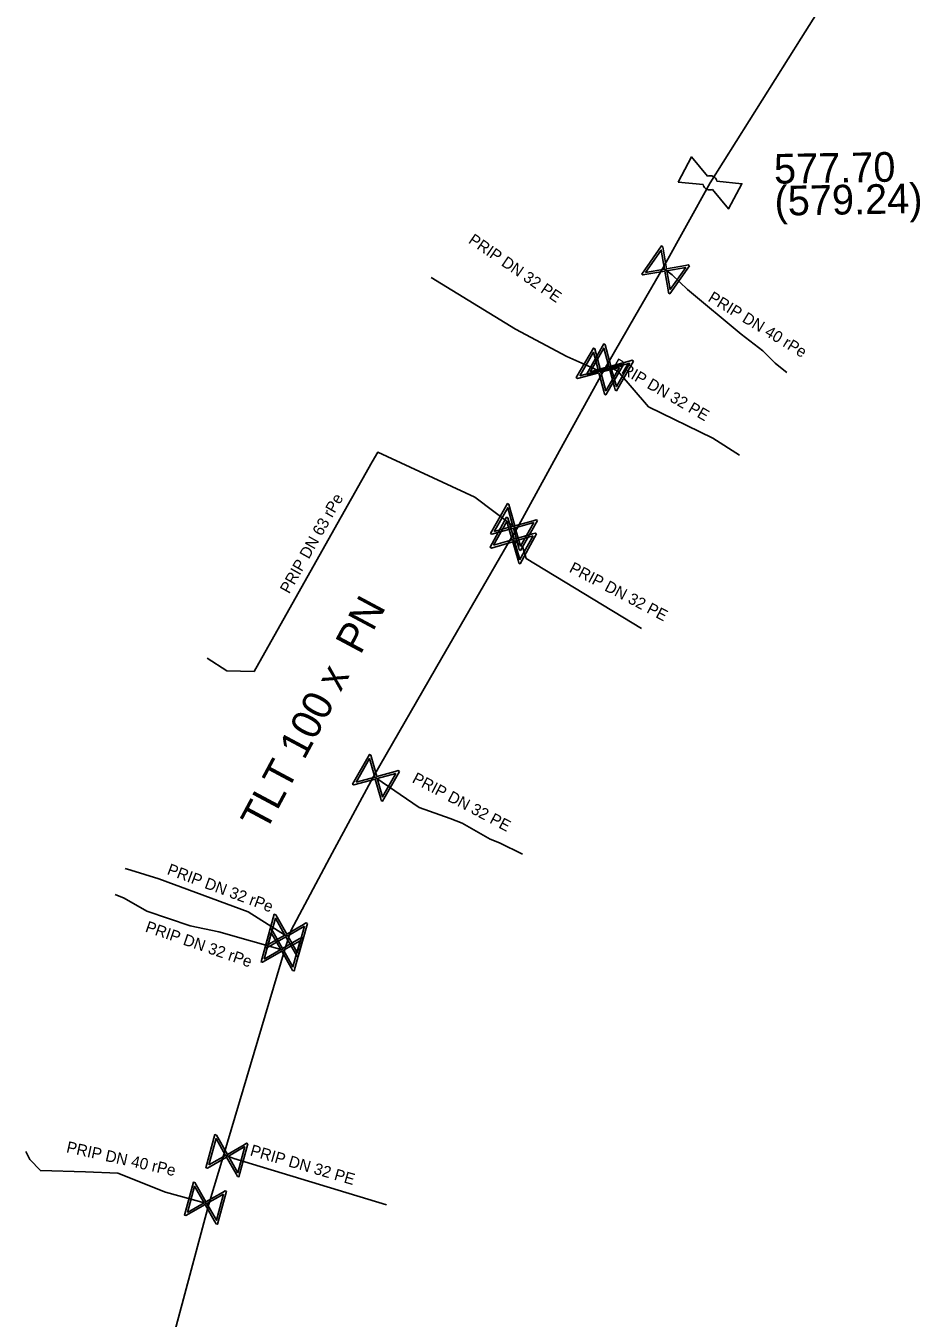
# Model space of a CAD drawing. Extents: x -643544 to -637295, y -1119190 to -1111715.
# Drawn here: x -641860.3 to -641821.1, y -1114876.1 to -1114819.6 of the extents above; entities that cross this region are included whole.
import ezdxf

# ---------------------------------------------------------------- set-up
doc = ezdxf.new("R2010")
doc.units = 0
for name, color, linetype in [('Default', 7, 'Continuous'), ('VP Lomový bod', 7, 'Continuous'), ('VP Lomový bod - popis', 7, 'Continuous'), ('VP Popis přípojky', 7, 'Continuous'), ('VP Přípojka', 7, 'Continuous'), ('VP Řad', 7, 'Continuous'), ('VP Řad - popis', 7, 'Continuous'), ('VP Šoupě', 7, 'Continuous')]:
    doc.layers.add(name, color=color, linetype=linetype)

msp = doc.modelspace()

# ---------------------------------------------------------------- linework, layer by layer
at = {"layer": 'Default'}
for points in [[(-641830.444, -1114826.137), (-641830.395, -1114826.119), (-641830.342, -1114826.117), (-641830.255, -1114826.116), (-641830.183, -1114826.154), (-641830.111, -1114826.193), (-641830.066, -1114826.264), (-641830.036, -1114826.31), (-641830.025, -1114826.361)], [(-641830.217, -1114826.721), (-641830.266, -1114826.741), (-641830.321, -1114826.742), (-641830.405, -1114826.744), (-641830.477, -1114826.706), (-641830.549, -1114826.667), (-641830.596, -1114826.594), (-641830.625, -1114826.55), (-641830.636, -1114826.498)]]:
    msp.add_open_spline(points, degree=3, dxfattribs=at)
at = {"layer": 'VP Lomový bod'}
for points in [[(-641831.727, -1114826.394), (-641831.139, -1114825.291), (-641830.444, -1114826.137)], [(-641830.636, -1114826.498), (-641831.727, -1114826.394)], [(-641830.025, -1114826.361), (-641828.933, -1114826.466), (-641829.521, -1114827.569), (-641830.217, -1114826.721)]]:
    msp.add_lwpolyline(points, dxfattribs=at)
at = {"layer": 'VP Přípojka'}
for points in [[(-641832.39, -1114830.16), (-641832.273, -1114830.238), (-641831.98, -1114830.45), (-641831.32, -1114831.1), (-641828.97, -1114833.05), (-641828.02, -1114833.78), (-641827.48, -1114834.32), (-641827.1, -1114834.63), (-641826.972, -1114834.735)], [(-641835.04, -1114834.75), (-641835.151, -1114834.676), (-641836.59, -1114834.03), (-641838.85, -1114832.84), (-641842.534, -1114830.571)], [(-641829.046, -1114838.345), (-641830.21, -1114837.6), (-641833.02, -1114836.23), (-641834.37, -1114834.67), (-641834.722, -1114834.486), (-641834.84, -1114834.41)], [(-641838.79, -1114841.57), (-641838.907, -1114841.492), (-641840.62, -1114840.19), (-641844.87, -1114838.22), (-641845.11, -1114838.64), (-641846.92, -1114841.85), (-641850.28, -1114847.81), (-641851.47, -1114847.79), (-641852.331, -1114847.228)], [(-641839.06, -1114842.02), (-641838.936, -1114842.085), (-641838.85, -1114842.13), (-641838.75, -1114842.21), (-641838.54, -1114842.35), (-641838.37, -1114842.87), (-641833.334, -1114845.941)], [(-641845.06, -1114852.41), (-641844.955, -1114852.478), (-641843.06, -1114853.77), (-641841.7, -1114854.25), (-641841.18, -1114854.45), (-641839.95, -1114855.15), (-641839.55, -1114855.31), (-641838.54, -1114855.81)], [(-641855.927, -1114856.434), (-641855.68, -1114856.51), (-641854.45, -1114856.89), (-641850.54, -1114858.34), (-641848.95, -1114859.35), (-641848.872, -1114859.366), (-641848.75, -1114859.39)], [(-641856.368, -1114857.574), (-641855.97, -1114857.74), (-641854.97, -1114858.3), (-641853.08, -1114858.95), (-641851.82, -1114859.21), (-641849.057, -1114860), (-641848.95, -1114860.03)], [(-641860.27, -1114868.82), (-641860.1, -1114869.17), (-641859.63, -1114869.66), (-641857.66, -1114869.72), (-641856.25, -1114869.77), (-641854.16, -1114870.61), (-641852.41, -1114871.09), (-641852.26, -1114871.13)], [(-641851.6, -1114868.96), (-641851.165, -1114869.129), (-641844.492, -1114871.16)]]:
    msp.add_lwpolyline(points, dxfattribs=at)
at = {"layer": 'VP Řad'}
msp.add_lwpolyline([(-641854.93, -1114881.05), (-641853.595, -1114876.09), (-641852.26, -1114871.13), (-641851.6, -1114868.96), (-641850.275, -1114864.495), (-641848.95, -1114860.03), (-641848.75, -1114859.39), (-641848.66, -1114859.14), (-641846.86, -1114855.775), (-641845.06, -1114852.41), (-641842.06, -1114847.215), (-641839.06, -1114842.02), (-641838.79, -1114841.57), (-641836.915, -1114838.16), (-641835.04, -1114834.75), (-641834.84, -1114834.41), (-641833.615, -1114832.285), (-641832.39, -1114830.16), (-641830.33, -1114826.43), (-641826.335, -1114820.09), (-641822.34, -1114813.75)], dxfattribs=at)
at = {"layer": 'VP Šoupě'}
for points in [[(-641831.228, -1114830.056), (-641832.091, -1114831.283), (-641832.145, -1114831.245), (-641832.163, -1114831.118), (-641832.308, -1114830.29), (-641833.264, -1114830.458), (-641833.318, -1114830.42), (-641832.455, -1114829.193), (-641832.401, -1114829.231), (-641832.236, -1114830.189), (-641831.409, -1114830.043), (-641831.282, -1114830.018), (-641831.228, -1114830.056)], [(-641833.154, -1114830.349), (-641832.323, -1114830.204), (-641832.468, -1114829.375), (-641833.154, -1114830.349)], [(-641831.395, -1114830.131), (-641832.221, -1114830.275), (-641832.077, -1114831.1), (-641831.395, -1114830.131)], [(-641833.68, -1114834.229), (-641834.428, -1114835.529), (-641834.485, -1114835.496), (-641834.514, -1114835.371), (-641834.734, -1114834.56), (-641835.671, -1114834.814), (-641835.728, -1114834.782), (-641834.981, -1114833.481), (-641834.924, -1114833.514), (-641834.672, -1114834.452), (-641833.862, -1114834.232), (-641833.737, -1114834.196), (-641833.68, -1114834.229)], [(-641834.133, -1114834.416), (-641834.89, -1114835.711), (-641834.947, -1114835.678), (-641834.976, -1114835.553), (-641835.19, -1114834.74), (-641836.128, -1114834.987), (-641836.185, -1114834.954), (-641835.428, -1114833.659), (-641835.371, -1114833.692), (-641835.127, -1114834.633), (-641834.314, -1114834.419), (-641834.19, -1114834.383), (-641834.133, -1114834.416)], [(-641836.027, -1114834.87), (-641835.212, -1114834.655), (-641835.426, -1114833.842), (-641836.027, -1114834.87)], [(-641835.571, -1114834.696), (-641834.757, -1114834.475), (-641834.978, -1114833.664), (-641835.571, -1114834.696)], [(-641834.293, -1114834.505), (-641835.104, -1114834.718), (-641834.891, -1114835.527), (-641834.293, -1114834.505)], [(-641833.84, -1114834.318), (-641834.649, -1114834.537), (-641834.43, -1114835.345), (-641833.84, -1114834.318)], [(-641837.884, -1114841.212), (-641838.627, -1114842.515), (-641838.685, -1114842.482), (-641838.715, -1114842.357), (-641838.937, -1114841.547), (-641839.873, -1114841.804), (-641839.93, -1114841.772), (-641839.187, -1114840.469), (-641839.129, -1114840.502), (-641838.875, -1114841.439), (-641838.065, -1114841.217), (-641837.941, -1114841.18), (-641837.884, -1114841.212)], [(-641839.773, -1114841.686), (-641838.96, -1114841.463), (-641839.183, -1114840.651), (-641839.773, -1114841.686)], [(-641837.917, -1114841.79), (-641838.641, -1114843.104), (-641838.698, -1114843.072), (-641838.73, -1114842.947), (-641838.965, -1114842.141), (-641839.897, -1114842.412), (-641839.955, -1114842.38), (-641839.231, -1114841.066), (-641839.174, -1114841.098), (-641838.905, -1114842.032), (-641838.099, -1114841.797), (-641837.975, -1114841.758), (-641837.917, -1114841.79)], [(-641839.799, -1114842.292), (-641838.99, -1114842.056), (-641839.225, -1114841.249), (-641839.799, -1114842.292)], [(-641838.043, -1114841.303), (-641838.852, -1114841.524), (-641838.63, -1114842.331), (-641838.043, -1114841.303)], [(-641838.075, -1114841.882), (-641838.881, -1114842.116), (-641838.646, -1114842.92), (-641838.075, -1114841.882)], [(-641843.926, -1114852.188), (-641844.666, -1114853.493), (-641844.724, -1114853.46), (-641844.754, -1114853.335), (-641844.978, -1114852.526), (-641845.914, -1114852.785), (-641845.971, -1114852.752), (-641845.231, -1114851.448), (-641845.173, -1114851.48), (-641844.917, -1114852.417), (-641844.107, -1114852.193), (-641843.983, -1114852.155), (-641843.926, -1114852.188)], [(-641845.814, -1114852.666), (-641845.002, -1114852.441), (-641845.226, -1114851.63), (-641845.814, -1114852.666)], [(-641844.085, -1114852.279), (-641844.893, -1114852.502), (-641844.67, -1114853.309), (-641844.085, -1114852.279)], [(-641847.951, -1114858.841), (-641848.347, -1114860.287), (-641848.41, -1114860.27), (-641848.47, -1114860.156), (-641848.887, -1114859.427), (-641849.73, -1114859.909), (-641849.793, -1114859.891), (-641849.397, -1114858.445), (-641849.334, -1114858.462), (-641848.854, -1114859.307), (-641848.125, -1114858.89), (-641848.014, -1114858.823), (-641847.951, -1114858.841)], [(-641849.663, -1114859.769), (-641848.931, -1114859.351), (-641849.348, -1114858.62), (-641849.663, -1114859.769)], [(-641848.083, -1114858.968), (-641848.811, -1114859.384), (-641848.395, -1114860.11), (-641848.083, -1114858.968)], [(-641848.136, -1114859.475), (-641848.532, -1114860.921), (-641848.595, -1114860.904), (-641848.655, -1114860.79), (-641849.072, -1114860.061), (-641849.915, -1114860.543), (-641849.978, -1114860.525), (-641849.582, -1114859.079), (-641849.519, -1114859.096), (-641849.039, -1114859.941), (-641848.31, -1114859.524), (-641848.199, -1114859.457), (-641848.136, -1114859.475)], [(-641849.848, -1114860.403), (-641849.116, -1114859.985), (-641849.533, -1114859.254), (-641849.848, -1114860.403)], [(-641848.268, -1114859.602), (-641848.996, -1114860.018), (-641848.58, -1114860.744), (-641848.268, -1114859.602)], [(-641850.549, -1114868.485), (-641850.945, -1114869.931), (-641851.008, -1114869.914), (-641851.068, -1114869.8), (-641851.485, -1114869.071), (-641852.328, -1114869.553), (-641852.391, -1114869.535), (-641851.995, -1114868.089), (-641851.932, -1114868.106), (-641851.452, -1114868.951), (-641850.723, -1114868.534), (-641850.612, -1114868.467), (-641850.549, -1114868.485)], [(-641852.261, -1114869.413), (-641851.529, -1114868.995), (-641851.946, -1114868.264), (-641852.261, -1114869.413)], [(-641850.681, -1114868.612), (-641851.409, -1114869.028), (-641850.993, -1114869.754), (-641850.681, -1114868.612)], [(-641851.489, -1114870.565), (-641851.885, -1114872.011), (-641851.948, -1114871.994), (-641852.008, -1114871.88), (-641852.425, -1114871.151), (-641853.268, -1114871.633), (-641853.331, -1114871.615), (-641852.935, -1114870.169), (-641852.872, -1114870.186), (-641852.392, -1114871.031), (-641851.663, -1114870.614), (-641851.552, -1114870.547), (-641851.489, -1114870.565)], [(-641853.201, -1114871.493), (-641852.469, -1114871.075), (-641852.886, -1114870.344), (-641853.201, -1114871.493)], [(-641851.621, -1114870.692), (-641852.349, -1114871.108), (-641851.933, -1114871.834), (-641851.621, -1114870.692)]]:
    msp.add_lwpolyline(points, dxfattribs=at)

# ---------------------------------------------------------------- texts
at = {"layer": 'VP Lomový bod - popis'}
for s, p in [('577.70', (-641827.522, -1114826.468)), ('(579.24)', (-641827.497, -1114827.867))]:
    msp.add_text(s, height=1.3, rotation=1, dxfattribs=at).set_placement(p)
at = {"layer": 'VP Popis přípojky'}
for s, rotation, p in [('PRIP DN 32 PE', 325.607, (-641840.942, -1114829.035)), ('PRIP DN 40 rPe', 328.7865, (-641830.456, -1114831.58)), ('PRIP DN 32 PE', 329.9363, (-641834.638, -1114834.513)), ('PRIP DN 63 rPe', 60.5875, (-641848.746, -1114844.449)), ('PRIP DN 32 PE', 332.2729, (-641836.53, -1114843.44)), ('PRIP DN 32 PE', 332.2973, (-641843.401, -1114852.649)), ('PRIP DN 32 rPe', 339.653, (-641854.125, -1114856.678)), ('PRIP DN 32 rPe', 341.0211, (-641855.079, -1114859.194)), ('PRIP DN 40 rPe', 347.5142, (-641858.528, -1114868.857)), ('PRIP DN 32 PE', 343.8834, (-641850.491, -1114868.989))]:
    msp.add_text(s, height=0.5, rotation=rotation, dxfattribs=at).set_placement(p)
at = {"layer": 'VP Řad - popis'}
msp.add_text('TLT 100 x  PN ', height=1.3, rotation=61.8569, dxfattribs=at).set_placement((-641849.777, -1114854.876))

doc.saveas('drawing.dxf')
